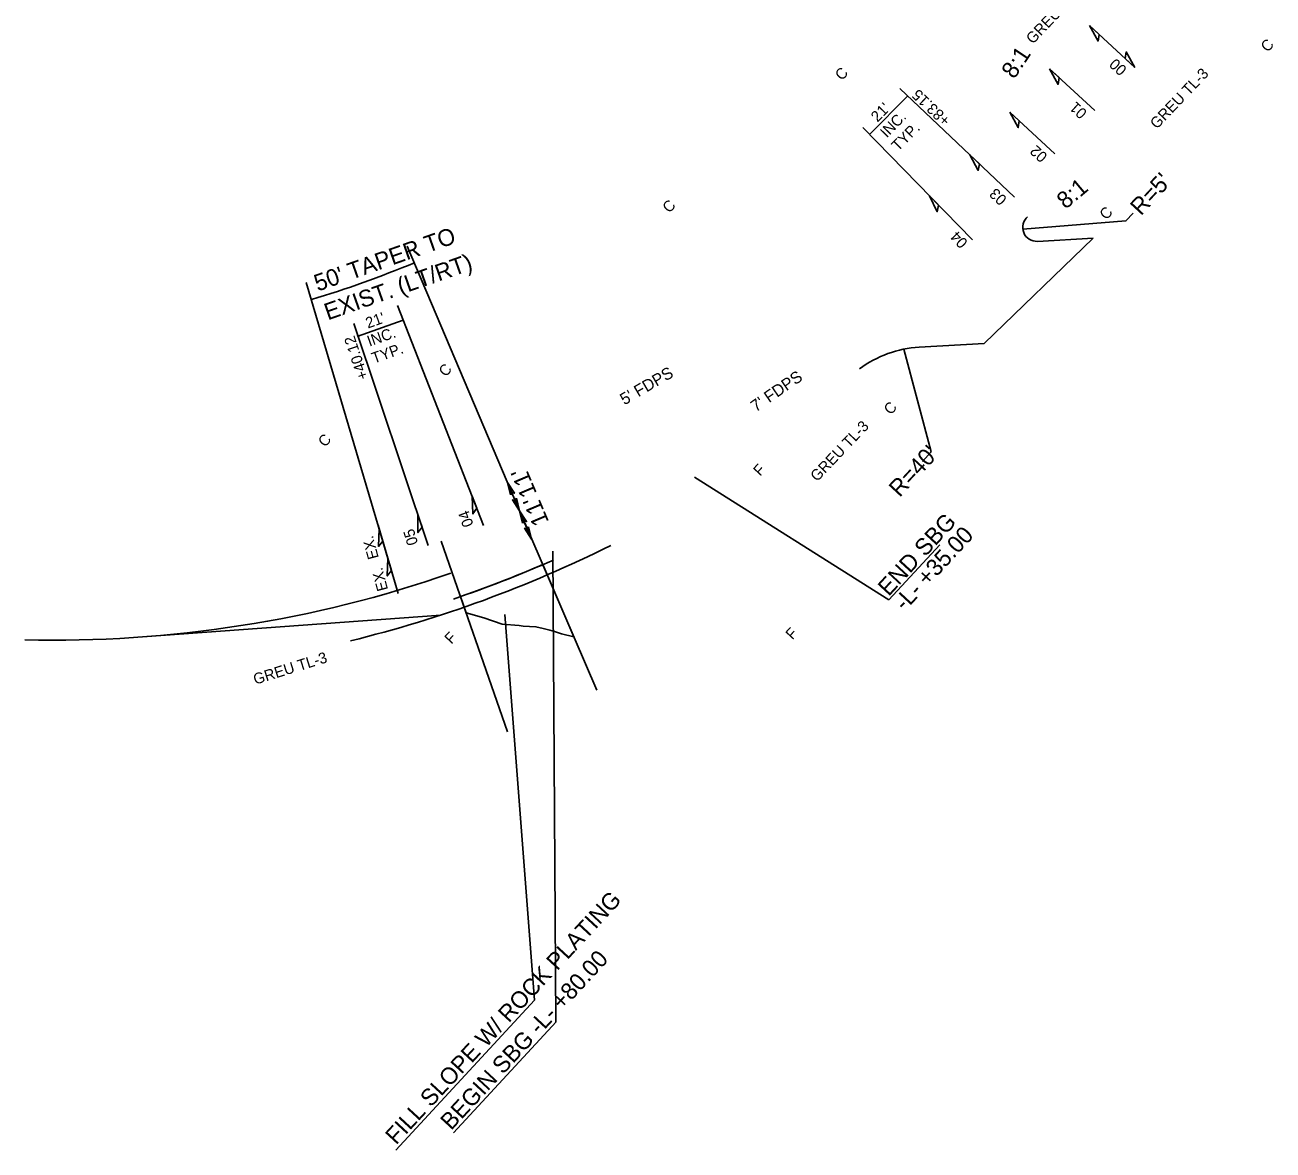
# Model space of a CAD drawing. Extents: x 1768470 to 1769391, y 999727 to 1000666.
# Drawn here: x 1768470.3 to 1768915.9, y 999727.5 to 1000129.2 of the extents above; entities that cross this region are included whole.
import ezdxf

# ---------------------------------------------------------------- set-up
doc = ezdxf.new("R2010")
doc.units = 0
for name, color, linetype in [('Cogo Default Point CELL', 7, 'Continuous'), ('COGO Default Point Number', 7, 'Continuous'), ('CTL Sheet Datum Description CELL', 7, 'Continuous'), ('E_ENV_WETLAND_BOUNDARY', 7, 'Continuous'), ('Exist Environmental Wetland Boundary', 7, 'Continuous'), ('Exist Environmental Wetland Boundary Cogo Number', 7, 'Continuous'), ('Exist Hydro Jurisdictional Stream or Body of Water', 7, 'Continuous'), ('Exist Property Line Leader', 7, 'Continuous'), ('P_HYD_Ditch_Flow_Arrow', 7, 'Continuous'), ('P_HYD_TC_Geotextile', 7, 'Continuous'), ('P_NCDOT_Terrain_Contour_Imported', 7, 'Continuous'), ('P_NCDOT_Terrain_Exterior', 7, 'Continuous'), ('Sheet Symbology CELL', 7, 'Continuous')]:
    doc.layers.add(name, color=color, linetype=linetype)

msp = doc.modelspace()

# ---------------------------------------------------------------- linework, layer by layer
at = {"layer": 'Cogo Default Point CELL'}
msp.add_line((1768596.52, 999950.01), (1768570.73, 1000037.24), dxfattribs=at)
msp.add_arc((1768454.09, 1000420.19), 406.74, 286.933, 292.4365, dxfattribs=at)
at = {"layer": 'CTL Sheet Datum Description CELL'}
for p, q in [((1768606.8, 1000050.2), (1768651.16, 999945.59)), ((1768778.76, 999923.93), (1768709.36, 999967.67)), ((1768659.84, 999773.14), (1768658.76, 999941.33)), ((1768778.76, 999923.93), (1768796.93, 999943.59)), ((1768652.24, 999780.98), (1768641.6, 999918.71)), ((1768602.76, 999727.46), (1768652.24, 999780.98)), ((1768623.33, 999733.64), (1768659.96, 999773.27))]:
    msp.add_line(p, q, dxfattribs=at)
for points in [[(1768865.94, 1000062), (1768863.37, 1000059.22), (1768826.53, 1000056.25)], [(1768790.72, 999973.31), (1768793.86, 999976.71), (1768784.11, 1000013.4)]]:
    msp.add_lwpolyline(points, dxfattribs=at)
at = {"layer": 'Exist Environmental Wetland Boundary Cogo Number'}
for points in [[(1768643.61, 999961.4), (1768642.57, 999965.84), (1768645.07, 999961.99), (1768644.11, 999962.21)], [(1768645.82, 999960.16), (1768646.86, 999955.72), (1768644.36, 999959.57), (1768645.32, 999959.35)], [(1768647.9, 999951.27), (1768646.86, 999955.72), (1768649.36, 999951.86), (1768648.4, 999952.08)], [(1768650.11, 999950.03), (1768651.16, 999945.59), (1768648.65, 999949.44), (1768649.61, 999949.23)]]:
    msp.add_lwpolyline(points, close=True, dxfattribs=at)
at = {"layer": 'Exist Hydro Jurisdictional Stream or Body of Water'}
msp.add_line((1768596.52, 999950.01), (1768602.97, 999928.22), dxfattribs=at)
at = {"layer": 'P_HYD_Ditch_Flow_Arrow'}
msp.add_lwpolyline([(1768630.59, 999926.76), (1768636.05, 999928.77), (1768640.38, 999930.43), (1768643, 999931.45), (1768646.08, 999932.69), (1768648.57, 999933.7), (1768652.43, 999935.31), (1768655.15, 999936.47), (1768666.27, 999910.65), (1768661.89, 999911.72), (1768659.39, 999912.63), (1768657.71, 999913.05), (1768655.32, 999913.67), (1768652.75, 999914.32), (1768648.11, 999914.49), (1768646.72, 999914.69), (1768640.72, 999915.17), (1768634.1, 999917.54), (1768627.8, 999919.32), (1768625.8, 999925.06)], close=True, dxfattribs=at)
at = {"layer": 'P_HYD_TC_Geotextile'}
msp.add_line((1768512.25, 999910.67), (1768618.74, 999918.46), dxfattribs=at)
for radius, start, end in [(445, 283.7571, 296.5218), (432, 268.6162, 289.1338)]:
    msp.add_arc((1768480.75, 1000341.52), radius, start, end, dxfattribs=at)
at = {"layer": 'P_NCDOT_Terrain_Contour_Imported'}
for p, q in [((1768674.44, 999891.68), (1768646.84, 999955.76)), ((1768642.62, 999876.76), (1768618.89, 999944.89))]:
    msp.add_line(p, q, dxfattribs=at)
msp.add_arc((1768480.75, 1000341.52), 441, 288.8538, 293.8333, dxfattribs=at)
at = {"layer": 'P_NCDOT_Terrain_Exterior'}
for p, q in [((1768850.36, 1000128.92), (1768866.52, 1000113.99)), ((1768836.11, 1000113.5), (1768852.26, 1000098.57)), ((1768782.68, 1000106.48), (1768823.62, 1000067.65)), ((1768771.98, 1000090.2), (1768785.34, 1000103.68)), ((1768821.85, 1000098.08), (1768838.01, 1000083.14)), ((1768769.46, 1000092.54), (1768808.57, 1000052.4)), ((1768603.25, 1000028.96), (1768634.01, 999950.48)), ((1768587.67, 1000022.63), (1768614.27, 999943.31)), ((1768588.9, 1000017.94), (1768605.28, 1000023.77)), ((1768596.36, 999950.57), (1768603.57, 999926.18)), ((1768596.73, 999949.31), (1768599.85, 999938.76)), ((1768599.85, 999938.76), (1768602.97, 999928.22))]:
    msp.add_line(p, q, dxfattribs=at)
for points in [[(1768850.36, 1000128.92), (1768853.41, 1000123.38), (1768853.76, 1000125.78)], [(1768866.52, 1000113.99), (1768863.47, 1000119.53), (1768863.12, 1000117.13)], [(1768836.11, 1000113.5), (1768839.16, 1000107.96), (1768839.5, 1000110.36)], [(1768821.85, 1000098.08), (1768824.9, 1000092.54), (1768825.25, 1000094.94)], [(1768807.67, 1000082.79), (1768810.64, 1000077.21), (1768811.02, 1000079.6)], [(1768793.22, 1000068.15), (1768795.97, 1000062.46), (1768796.44, 1000064.84)], [(1768629.92, 999960.9), (1768630.25, 999954.59), (1768631.61, 999956.6)], [(1768610.61, 999954.24), (1768610.62, 999947.91), (1768612.08, 999949.85)], [(1768596.73, 999949.31), (1768596.52, 999942.99), (1768598.04, 999944.88)], [(1768599.85, 999938.76), (1768599.64, 999932.44), (1768601.16, 999934.33)]]:
    msp.add_lwpolyline(points, close=True, dxfattribs=at)
at = {"layer": 'Sheet Symbology CELL'}
for p, q in [((1768851.66, 1000053.06), (1768812.7, 1000015.45)), ((1768851.66, 1000053.06), (1768831.78, 1000051.9)), ((1768812.7, 1000015.45), (1768789.58, 1000014.1))]:
    msp.add_line(p, q, dxfattribs=at)
for centre, radius, start, end in [((1768831.49, 1000056.89), 5, 130.1263, 273.3407), ((1768791.91, 999974.17), 40, 93.3407, 126.2865)]:
    msp.add_arc(centre, radius, start, end, dxfattribs=at)

# ---------------------------------------------------------------- texts
at = {"layer": 'Cogo Default Point CELL'}
for s, height, rotation, p in [('8:1', 6, 56.1557, (1768823.46, 1000109.59)), ('8:1', 6, 39.8824, (1768841.79, 1000063.17)), ("R=5'", 6, 47.2512, (1768868.71, 1000060.8)), ("50' TAPER TO", 6, 19.3664, (1768574.81, 1000033.95)), ('EXIST. (LT/RT)', 6, 19.3664, (1768578.43, 1000023.66)), ("5' FDPS", 4.2, 30.2236, (1768684.29, 999993.31)), ("7' FDPS", 4.2, 34.6453, (1768731.25, 999990.81)), ("R=40'", 6, 47.2512, (1768782.56, 999960.25)), ("11'", 6, 112.9799, (1768653.17, 999961.98)), ("11'", 6, 112.9799, (1768657.49, 999951.79)), ('END SBG', 6, 47.2512, (1768778.64, 999924.92)), ('-L- +35.00', 6, 47.2512, (1768784.37, 999919.62)), ('FILL SLOPE W/ ROCK PLATING', 6, 47.2512, (1768602.81, 999729.06)), ('BEGIN SBG -L- +80.00', 6, 47.2512, (1768622.47, 999734.25))]:
    msp.add_text(s, height=height, rotation=rotation, dxfattribs=at).set_placement(p)
at = {"layer": 'COGO Default Point Number'}
for p in [(1768913.94, 1000119.2), (1768761.95, 1000109.07), (1768700.35, 1000061.77), (1768856.37, 1000059.32), (1768620.48, 1000003.27), (1768779.36, 999989.7), (1768577.4, 999978.19)]:
    msp.add_text('C', height=3.9, rotation=47.2512, dxfattribs=at).set_placement(p)
at = {"layer": 'E_ENV_WETLAND_BOUNDARY'}
for rotation, p in [(46.4043, (1768830.12, 1000122.11)), (46.4043, (1768874.39, 1000091.78)), (46.4043, (1768753.11, 999965.89)), (17.3807, (1768552.56, 999893.57))]:
    msp.add_text('GREU TL-3', height=3.9, rotation=rotation, dxfattribs=at).set_placement(p)
at = {"layer": 'Exist Environmental Wetland Boundary'}
for s, rotation, p in [('00', 137.7129, (1768863.96, 1000113.6)), ('+83.15', 136.639, (1768800.97, 1000095.48)), ("21' ", 45.2582, (1768774.66, 1000094.23)), ('01', 137.7129, (1768849.76, 1000098.13)), ('INC.', 45.2582, (1768777.94, 1000088.64)), ('TYP.', 45.2582, (1768782.02, 1000083.86)), ('02', 137.7129, (1768835.63, 1000082.6)), ('03', 136.9788, (1768821.12, 1000067.25)), ('04', 132.8146, (1768807.14, 1000051.65)), ("21'", 19.5972, (1768592.74, 1000020.74)), ('INC.', 19.5972, (1768593.28, 1000014.29)), ('+40.12', 108.5371, (1768592.98, 1000003.25)), ('TYP.', 19.5972, (1768594.89, 1000008.21)), ('04', 109.9642, (1768630.52, 999950.73)), ('05', 107.0994, (1768610.7, 999944.05)), ('EX.', 105.0368, (1768596.65, 999938.97)), ('EX.', 105.0368, (1768599.97, 999927.6))]:
    msp.add_text(s, height=3.9, rotation=rotation, dxfattribs=at).set_placement(p)
at = {"layer": 'Exist Property Line Leader'}
for p in [(1768732.78, 999967.83), (1768622.56, 999907.86), (1768744.31, 999909.41)]:
    msp.add_text('F', height=3.9, rotation=47.2512, dxfattribs=at).set_placement(p)

doc.saveas('drawing.dxf')
